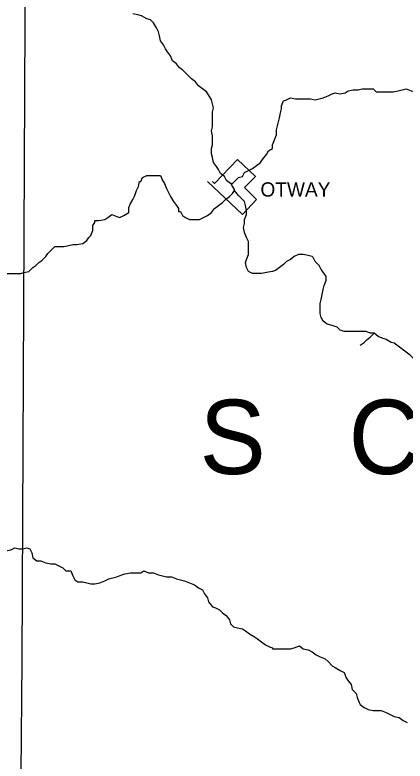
# Model space of a CAD drawing. Extents: x 0 to 34, y 0 to 22.
# Drawn here: x 5.076 to 5.61, y 16.176 to 17.195 of the extents above; entities that cross this region are included whole.
import ezdxf

# ---------------------------------------------------------------- set-up
doc = ezdxf.new("R2010")
doc.units = 0
doc.layers.add('Default', color=7, linetype='Continuous')
doc.layers.add('TR_Turning_Path1', color=7, linetype='Continuous')

msp = doc.modelspace()

# ---------------------------------------------------------------- linework, layer by layer
at = {"layer": 'Default'}
for points in [[(5.0874, 17.6276), (5.0915, 17.3603), (5.0901, 17.1858), (5.086, 16.3132), (5.0847, 16.1592), (5.0819, 15.8442)], [(5.3137, 17.1122), (5.311, 17.1149), (5.3055, 17.1204), (5.3014, 17.1231), (5.2974, 17.1285), (5.2919, 17.1326), (5.2892, 17.1395), (5.2851, 17.1449), (5.2824, 17.149), (5.2796, 17.1544), (5.2755, 17.1599), (5.2742, 17.1667), (5.2728, 17.1722), (5.2701, 17.1776), (5.266, 17.1844), (5.2619, 17.1885), (5.2565, 17.1899), (5.2496, 17.194), (5.2442, 17.1954), (5.2374, 17.1967)], [(5.3723, 16.9636), (5.3723, 16.9649), (5.371, 16.9649), (5.3655, 16.969), (5.3628, 16.9745), (5.3573, 16.9786), (5.3546, 16.984), (5.3519, 16.9881), (5.3478, 16.9936), (5.3464, 17.0004), (5.3451, 17.0058), (5.3451, 17.0127), (5.3464, 17.0181), (5.3464, 17.0249), (5.3464, 17.0304), (5.3451, 17.0372), (5.3464, 17.0426), (5.3464, 17.0495), (5.3464, 17.0549), (5.3464, 17.0631), (5.3478, 17.0686), (5.3464, 17.074), (5.3451, 17.0795), (5.341, 17.0863), (5.3383, 17.0904), (5.3328, 17.0945), (5.3273, 17.0985), (5.3233, 17.104), (5.3178, 17.1081), (5.3137, 17.1122)], [(5.4405, 17.0713), (5.4432, 17.0781), (5.4473, 17.0795), (5.4528, 17.0822), (5.4596, 17.0808), (5.4664, 17.0808), (5.4732, 17.0808), (5.4801, 17.0808), (5.4869, 17.0795), (5.4923, 17.0808), (5.4978, 17.0822), (5.5046, 17.0849), (5.51, 17.0876), (5.5141, 17.089), (5.521, 17.0876), (5.5278, 17.089), (5.5319, 17.0917), (5.5387, 17.0931), (5.5455, 17.0931), (5.551, 17.0945), (5.5591, 17.0945), (5.5659, 17.0945), (5.57, 17.0904), (5.5769, 17.0904), (5.5782, 17.0904), (5.5809, 17.0904)], [(5.5809, 17.0904), (5.5864, 17.0904), (5.5932, 17.0904), (5.6, 17.0917), (5.6055, 17.0931), (5.6109, 17.0945), (5.6178, 17.0917), (5.6246, 17.0904), (5.6287, 17.0863), (5.6355, 17.0849), (5.6409, 17.0836), (5.6491, 17.0822), (5.6546, 17.0808), (5.66, 17.0808), (5.6668, 17.0795), (5.6709, 17.0781), (5.6737, 17.0713), (5.6737, 17.0645), (5.675, 17.0576), (5.6764, 17.0549), (5.6764, 17.0549)], [(5.3723, 16.9636), (5.3764, 16.9677), (5.3819, 16.9731), (5.3873, 16.9745), (5.3901, 16.9799), (5.3955, 16.9827), (5.401, 16.9854), (5.4064, 16.9895), (5.4119, 16.9936), (5.4146, 16.9977), (5.4201, 17.0045), (5.4228, 17.0099), (5.4282, 17.0127), (5.4282, 17.0181), (5.431, 17.0249), (5.4337, 17.0317), (5.4337, 17.0386), (5.4351, 17.044), (5.4364, 17.0495), (5.4378, 17.0549), (5.4392, 17.0617), (5.4405, 17.0672), (5.4405, 17.0713), (5.4405, 17.0713)], [(5.3464, 16.9677), (5.3492, 16.9649), (5.3805, 16.9977), (5.4051, 16.9745), (5.3901, 16.9595), (5.4064, 16.9431), (5.3873, 16.9227), (5.3396, 16.9677)], [(5.2483, 16.9677), (5.251, 16.9731), (5.2565, 16.9758), (5.2619, 16.9758), (5.2674, 16.9758), (5.2755, 16.9758), (5.2783, 16.969), (5.281, 16.9649), (5.2837, 16.9581), (5.2864, 16.9527), (5.2892, 16.9472), (5.2933, 16.9404), (5.2974, 16.9349), (5.3001, 16.9308), (5.3001, 16.9268), (5.3028, 16.9268)], [(5.1856, 16.9145), (5.191, 16.9145), (5.1992, 16.9158), (5.2033, 16.9186), (5.2087, 16.9227), (5.2155, 16.9199), (5.2196, 16.9186), (5.2251, 16.9213), (5.2319, 16.9254), (5.2319, 16.9322), (5.2346, 16.9377), (5.2374, 16.9431), (5.2401, 16.9486), (5.2428, 16.9554), (5.2455, 16.9608), (5.2469, 16.9677), (5.2483, 16.9677)], [(5.3764, 16.9554), (5.3764, 16.9568), (5.3723, 16.9636)], [(5.3764, 16.9554), (5.3764, 16.9568), (5.3723, 16.9636)], [(5.3028, 16.9268), (5.3055, 16.9213), (5.3096, 16.9186), (5.3151, 16.9158), (5.3219, 16.9158), (5.3287, 16.9158), (5.3342, 16.9186), (5.3396, 16.9213), (5.3451, 16.9254), (5.3492, 16.9308), (5.3546, 16.9349), (5.3601, 16.939), (5.3642, 16.9431), (5.3696, 16.9472), (5.3737, 16.9513), (5.3764, 16.9554)], [(5.4841, 16.864), (5.4841, 16.864), (5.4828, 16.8654), (5.4828, 16.8654), (5.4773, 16.8668), (5.4705, 16.8681), (5.4637, 16.8681), (5.4582, 16.8654), (5.4528, 16.8613), (5.4473, 16.8586), (5.4432, 16.8545), (5.4378, 16.8504), (5.4323, 16.8463), (5.4282, 16.845), (5.4201, 16.8436), (5.4132, 16.8422), (5.4078, 16.8422), (5.401, 16.8422), (5.3955, 16.845), (5.3928, 16.8504), (5.3914, 16.8572), (5.3928, 16.8613), (5.3955, 16.8681), (5.3955, 16.8736), (5.3955, 16.879), (5.3955, 16.8859), (5.3928, 16.8913), (5.3901, 16.8981), (5.3887, 16.9049), (5.3901, 16.9104), (5.3901, 16.9158), (5.3928, 16.9227), (5.3928, 16.9281), (5.3914, 16.9349), (5.3901, 16.9404), (5.386, 16.9445), (5.3819, 16.9486), (5.3764, 16.9554)], [(5.0888, 16.8436), (5.0956, 16.845), (5.101, 16.8504), (5.1051, 16.8531), (5.1092, 16.8572), (5.1133, 16.8599), (5.1187, 16.8654), (5.1215, 16.8695), (5.1269, 16.8749), (5.131, 16.879), (5.1365, 16.879), (5.1433, 16.879), (5.1501, 16.8804), (5.1556, 16.8818), (5.161, 16.8818), (5.1692, 16.8831), (5.1746, 16.8872), (5.1774, 16.8913), (5.1801, 16.894), (5.1828, 16.9009), (5.1828, 16.9077), (5.1856, 16.9118), (5.1856, 16.9145), (5.1856, 16.9145)], [(5.5373, 16.7631), (5.536, 16.7631), (5.5332, 16.7631), (5.5264, 16.7631), (5.521, 16.7645), (5.5169, 16.7686), (5.51, 16.7713), (5.5032, 16.7727), (5.4978, 16.7768), (5.4951, 16.7822), (5.4937, 16.7877), (5.4937, 16.7945), (5.4937, 16.8013), (5.4951, 16.8068), (5.4964, 16.8136), (5.4978, 16.8204), (5.4991, 16.8259), (5.5019, 16.8327), (5.5019, 16.8381), (5.4991, 16.8422), (5.4951, 16.8477), (5.4923, 16.8531), (5.4869, 16.8586), (5.4841, 16.864)], [(5.0438, 16.8422), (5.0465, 16.8463), (5.0519, 16.845), (5.0601, 16.8436), (5.0656, 16.8422), (5.071, 16.8422), (5.0778, 16.8422), (5.0847, 16.8422), (5.0888, 16.8436), (5.0888, 16.8436)], [(5.5673, 16.7604), (5.5619, 16.7604), (5.5564, 16.7631), (5.551, 16.7631), (5.5428, 16.7631), (5.5373, 16.7631)], [(5.5482, 16.7441), (5.5537, 16.7481), (5.5578, 16.7522), (5.5619, 16.755), (5.5659, 16.7591), (5.5673, 16.7604)], [(5.6437, 16.71), (5.6423, 16.7113), (5.6409, 16.7113), (5.6341, 16.7141), (5.63, 16.7182), (5.6246, 16.7222), (5.6205, 16.7263), (5.6164, 16.7304), (5.6109, 16.7345), (5.6055, 16.7386), (5.6, 16.7427), (5.5946, 16.7468), (5.5905, 16.7481), (5.5837, 16.7522), (5.5782, 16.7536), (5.5728, 16.7563), (5.5673, 16.7604)], [(5.0288, 16.4741), (5.0342, 16.4741), (5.0383, 16.47), (5.0438, 16.4686), (5.0492, 16.4646), (5.0547, 16.4605), (5.0601, 16.4591), (5.0642, 16.4632), (5.071, 16.4646), (5.0765, 16.4673), (5.0819, 16.4659), (5.0847, 16.4659), (5.0874, 16.4659)], [(5.0874, 16.4659), (5.0928, 16.4673), (5.0969, 16.4659), (5.0997, 16.4605), (5.101, 16.4537), (5.1065, 16.4496), (5.1119, 16.4496), (5.1187, 16.4468), (5.1256, 16.4455), (5.131, 16.4455), (5.1365, 16.4427), (5.1419, 16.44), (5.146, 16.4359), (5.1528, 16.4359), (5.1556, 16.4291), (5.1583, 16.4237), (5.1624, 16.4209), (5.1692, 16.4209), (5.1746, 16.4196), (5.1746, 16.4196)], [(5.1746, 16.4196), (5.1801, 16.4182), (5.1856, 16.4182), (5.1924, 16.4196), (5.1992, 16.4223), (5.2046, 16.425), (5.2101, 16.4264), (5.2155, 16.4277), (5.2224, 16.4305), (5.2265, 16.4318), (5.2346, 16.4332), (5.2415, 16.4332), (5.2483, 16.4332), (5.2524, 16.4359), (5.2592, 16.4332), (5.266, 16.4332), (5.2728, 16.4305), (5.2783, 16.4291), (5.2837, 16.4277), (5.2905, 16.4277), (5.2974, 16.425), (5.3028, 16.4237), (5.3083, 16.4223), (5.3151, 16.4196), (5.3219, 16.4168), (5.3219, 16.4168), (5.3219, 16.4168)], [(5.3219, 16.4168), (5.3273, 16.4127), (5.3328, 16.41), (5.3355, 16.4046), (5.3396, 16.3991), (5.341, 16.3937), (5.3464, 16.3868), (5.3505, 16.3855), (5.356, 16.3828), (5.3601, 16.3787), (5.3655, 16.3746), (5.3696, 16.3691), (5.371, 16.3637), (5.3751, 16.3596), (5.3805, 16.3582), (5.3873, 16.3568), (5.3914, 16.3541), (5.3969, 16.35), (5.4037, 16.3459), (5.4078, 16.3432), (5.4132, 16.3391), (5.4187, 16.335), (5.4242, 16.3323), (5.4282, 16.3309), (5.4282, 16.3296)], [(5.4282, 16.3296), (5.4337, 16.3296), (5.4405, 16.3296), (5.446, 16.3296), (5.4528, 16.3296), (5.4582, 16.3309), (5.4651, 16.3337), (5.4705, 16.3296), (5.4773, 16.3282), (5.4828, 16.3255), (5.4882, 16.3214), (5.4937, 16.3187), (5.5005, 16.3159), (5.5046, 16.3119), (5.51, 16.3064), (5.5141, 16.3037), (5.521, 16.2996), (5.5264, 16.2969), (5.5291, 16.29), (5.5319, 16.2859), (5.536, 16.2805), (5.5373, 16.2737), (5.5428, 16.2682), (5.5441, 16.2628), (5.5469, 16.256), (5.5482, 16.2532)], [(5.5482, 16.2532), (5.5537, 16.2491), (5.5591, 16.2464), (5.5659, 16.245), (5.5714, 16.245), (5.5769, 16.245), (5.5837, 16.2423), (5.5891, 16.2396), (5.5946, 16.2369), (5.6014, 16.2355), (5.6069, 16.2314), (5.6123, 16.2287)]]:
    msp.add_lwpolyline(points, dxfattribs=at)
msp.add_spline([(6.6853, 15.6179), (6.6553, 15.637), (6.6308, 15.656), (6.5994, 15.6806), (6.579, 15.7174), (6.5653, 15.7529), (6.5531, 15.7842), (6.5435, 15.8306), (6.5381, 15.8701), (6.5381, 15.9124), (6.5381, 15.9505), (6.5353, 16.0024), (6.5217, 16.0433), (6.5108, 16.0773), (6.4944, 16.1033), (6.4781, 16.1223), (6.4699, 16.1496), (6.4699, 16.1919), (6.4835, 16.2273), (6.4931, 16.2696), (6.4931, 16.3132), (6.4863, 16.3555), (6.4835, 16.3964), (6.4672, 16.4264), (6.4494, 16.4427), (6.4222, 16.4577), (6.4058, 16.4605), (6.3799, 16.4523), (6.3663, 16.4496), (6.3308, 16.44), (6.294, 16.4318), (6.2599, 16.4155), (6.2327, 16.3964), (6.2068, 16.38), (6.1754, 16.3623), (6.1495, 16.3473), (6.1304, 16.3364), (6.1072, 16.3282), (6.0718, 16.3296), (6.0377, 16.3364), (6.0036, 16.3391), (5.9654, 16.3459), (5.9395, 16.3282), (5.9163, 16.3105), (5.8973, 16.2696), (5.8795, 16.245), (5.8564, 16.2096), (5.8373, 16.1755), (5.8141, 16.166), (5.7746, 16.1496), (5.7418, 16.1332), (5.7009, 16.121), (5.6737, 16.106), (5.6368, 16.0896), (5.615, 16.0596), (5.6028, 16.0351), (5.5891, 15.9996), (5.5796, 15.9655), (5.5769, 15.9246), (5.5455, 15.896), (5.5114, 15.8701), (5.4637, 15.8469), (5.4132, 15.8469), (5.3723, 15.8387), (5.3273, 15.8387), (5.2837, 15.8442), (5.2428, 15.8633), (5.2169, 15.881), (5.1828, 15.8878), (5.1569, 15.8892), (5.1392, 15.8728), (5.1051, 15.8619), (5.0819, 15.8442)], degree=3, dxfattribs=at)

# ---------------------------------------------------------------- texts
msp.add_text('OTWAY', height=0.0195, dxfattribs=at).set_placement((5.4119, 16.9472))
at = {"layer": 'TR_Turning_Path1'}
msp.add_text('S   C   I   O   T   O', height=0.101489, dxfattribs=at).set_placement((5.3287, 16.5682))

doc.saveas('drawing.dxf')
